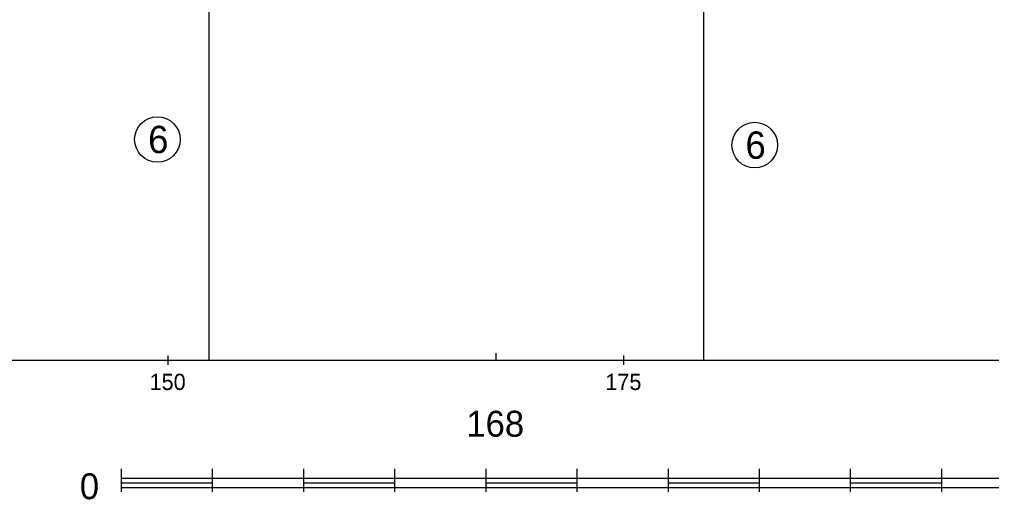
# Model space of a CAD drawing. Extents: x 3042 to 4120, y 576 to 2694.
# Drawn here: x 3354.9 to 3408.2, y 1243.9 to 1270.2 of the extents above; entities that cross this region are included whole.
import ezdxf

# ---------------------------------------------------------------- set-up
doc = ezdxf.new("R2010")
doc.units = 0
for name, color, linetype in [('14', 7, 'Continuous'), ('18', 7, 'Continuous'), ('7', 7, 'Continuous'), ('8', 7, 'Continuous'), ('pomocna', 7, 'Continuous'), ('rozhraní', 7, 'Continuous')]:
    doc.layers.add(name, color=color, linetype=linetype)

msp = doc.modelspace()

# ---------------------------------------------------------------- linework, layer by layer
at = {"layer": '18'}
msp.add_line((3380.987, 1251.926), (3380.987, 1251.545), dxfattribs=at)
at = {"layer": '7'}
for p, q in [((3363.007, 1251.291), (3363.007, 1251.799)), ((3388.007, 1251.291), (3388.007, 1251.799)), ((3213.007, 1251.545), (3557.897, 1251.545))]:
    msp.add_line(p, q, dxfattribs=at)
at = {"layer": '8'}
for p, q in [((3360.452, 1244.306), (3360.452, 1245.576)), ((3365.452, 1244.306), (3365.452, 1245.576)), ((3370.452, 1244.306), (3370.452, 1245.576)), ((3375.452, 1244.306), (3375.452, 1245.576)), ((3380.452, 1244.306), (3380.452, 1245.576)), ((3385.452, 1244.306), (3385.452, 1245.576)), ((3390.452, 1244.306), (3390.452, 1245.576)), ((3395.452, 1244.306), (3395.452, 1245.576)), ((3400.452, 1244.306), (3400.452, 1245.576)), ((3405.452, 1244.306), (3405.452, 1245.576)), ((3360.452, 1245.068), (3410.452, 1245.068)), ((3360.452, 1244.814), (3365.452, 1244.814)), ((3370.452, 1244.814), (3375.452, 1244.814)), ((3380.452, 1244.814), (3385.452, 1244.814)), ((3390.452, 1244.814), (3395.452, 1244.814)), ((3400.452, 1244.814), (3405.452, 1244.814)), ((3360.452, 1244.56), (3410.452, 1244.56))]:
    msp.add_line(p, q, dxfattribs=at)
at = {"layer": 'pomocna'}
for p, q in [((3365.26, 1251.545), (3365.26, 1313.095)), ((3392.39, 1251.545), (3392.39, 1313.195))]:
    msp.add_line(p, q, dxfattribs=at)
at = {"layer": 'rozhraní'}
for centre in [(3362.424, 1263.648), (3395.19, 1263.338)]:
    msp.add_circle(centre, 1.25, dxfattribs=at)

# ---------------------------------------------------------------- texts
at = {"layer": '14'}
msp.add_text('168', height=1.4224, dxfattribs=at).set_placement((3379.367, 1247.339))
at = {"layer": '7'}
for s, p in [('150', (3361.991, 1249.901)), ('175', (3386.991, 1249.901))]:
    msp.add_text(s, height=0.889, dxfattribs=at).set_placement(p)
at = {"layer": '8'}
msp.add_text('0', height=1.422, dxfattribs=at).set_placement((3358.166, 1243.91))
at = {"layer": 'rozhraní'}
for p in [(3361.913, 1262.898), (3394.679, 1262.588)]:
    msp.add_text('6', height=1.5, dxfattribs=at).set_placement(p)

doc.saveas('drawing.dxf')
